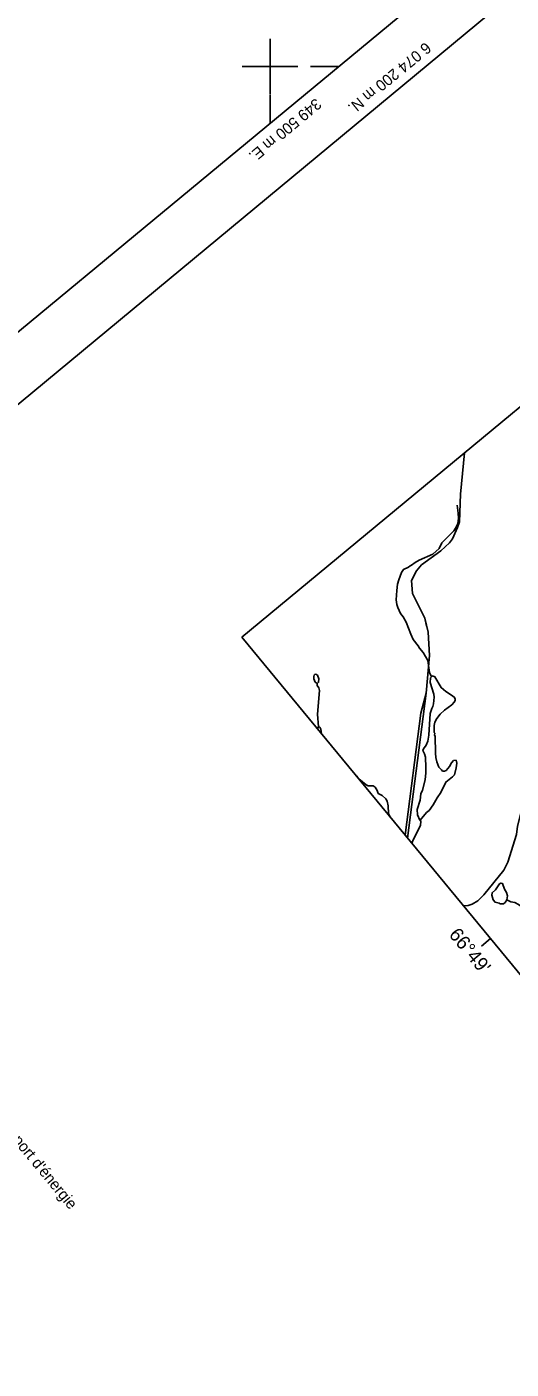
# Model space of a CAD drawing. Extents: x 347312 to 350503, y 6073086 to 6076432.
# Drawn here: x 349412.5 to 349586.7, y 6073732 to 6074214.3 of the extents above; entities that cross this region are included whole.
import ezdxf

# ---------------------------------------------------------------- set-up
doc = ezdxf.new("R2010")
doc.units = 0
for name, color, linetype in [('Level 60', 7, 'Continuous'), ('Level 61', 7, 'Continuous'), ('Level 63', 7, 'Continuous')]:
    doc.layers.add(name, color=color, linetype=linetype)

msp = doc.modelspace()

# ---------------------------------------------------------------- linework, layer by layer
at = {"layer": 'Level 60'}
for p, q in [((349514.56, 6074200), (349524.56, 6074200)), ((349500, 6074189.71), (349500, 6074179.71))]:
    msp.add_line(p, q, dxfattribs=at)
for points in [[(348779.44, 6073584.28), (350085.28, 6074663.34), (348652.09, 6076397.74), (347346.25, 6075318.68)], [(350097.64, 6074648.45), (350470.23, 6074198.33), (349166.42, 6073119.09), (348793.83, 6073569.21)]]:
    msp.add_lwpolyline(points, close=True, dxfattribs=at)
at = {"layer": 'Level 61'}
for p, q in [((349500, 6074210), (349500, 6074190)), ((349490, 6074200), (349510, 6074200))]:
    msp.add_line(p, q, dxfattribs=at)
at = {"layer": 'Level 63'}
for p, q in [((349549.45, 6073922.83), (349556.11, 6073974.87)), ((349579.28, 6073886.73), (349576, 6073884.02))]:
    msp.add_line(p, q, dxfattribs=at)
msp.add_lwpolyline([(349489.82, 6073994.99), (349706.59, 6073732.65), (349903.35, 6073895.24), (349686.57, 6074157.57)], close=True, dxfattribs=at)
for points in [[(349556.11, 6073974.87), (349557.36, 6073988.44), (349556.87, 6073996.73), (349555.61, 6074001.76), (349551.26, 6074010.63), (349550.92, 6074015.3), (349552.64, 6074018.82), (349554.49, 6074020.94), (349561.41, 6074025.98), (349564.57, 6074028.91), (349565.67, 6074030.33), (349567.47, 6074034.36), (349568.08, 6074036.4), (349568.52, 6074046.41), (349569.99, 6074061.24)], [(349567.3, 6074042.46), (349567.68, 6074039.51), (349567.75, 6074037.78), (349567.49, 6074035.78), (349566.94, 6074034.48), (349566.13, 6074033.24), (349561.84, 6074028.87), (349560.85, 6074026.89), (349558.58, 6074024.82), (349553.66, 6074022.61), (349552.2, 6074021.84), (349550.87, 6074020.85), (349550.37, 6074020.66), (349549.76, 6074020.13), (349547.97, 6074019.31), (349547.33, 6074018.2), (349546.29, 6074015.54), (349545.87, 6074014.07), (349545.54, 6074011.75), (349545.3, 6074008.35), (349545.56, 6074006.72), (349545.91, 6074005.59), (349546.97, 6074003.49), (349547.9, 6074002.33), (349548.94, 6074000.39), (349550.59, 6073996.11), (349551.49, 6073994.21), (349553.31, 6073991.85), (349553.75, 6073991.01), (349555.09, 6073989.46), (349556.76, 6073986.66), (349557.31, 6073982.27), (349558.04, 6073980.79)], [(349551.56, 6074010), (349555.61, 6074001.76), (349556.32, 6073998.93)], [(349615.7, 6073990.32), (349613.36, 6073988.48), (349611.61, 6073985.95), (349611.09, 6073980.65), (349609.87, 6073977.74), (349607.92, 6073975.06), (349602.95, 6073969.88), (349599.93, 6073965.27), (349598.84, 6073960.55), (349598.56, 6073955.83), (349593.82, 6073943.99), (349591.38, 6073936.59), (349589, 6073927.11), (349588.68, 6073924.15), (349585.58, 6073914.21), (349584.03, 6073911.25), (349576.84, 6073902.36), (349574.68, 6073900.22), (349572.74, 6073899.12), (349571.25, 6073898.59), (349569.6, 6073898.44)], [(349516.96, 6073978.35), (349517.43, 6073978.78), (349517.58, 6073980.03), (349517.06, 6073981.3), (349516.65, 6073981.62), (349516.2, 6073981.71), (349515.83, 6073981.36), (349515.68, 6073980.86), (349515.73, 6073979.97), (349516.2, 6073978.83), (349516.96, 6073978.35)], [(349516.96, 6073978.35), (349516.97, 6073977.65), (349517.57, 6073976.82), (349517.72, 6073975.8), (349517.09, 6073967.28), (349517.41, 6073962.76)], [(349553.81, 6073929.22), (349553.97, 6073929.29), (349556.22, 6073931.94), (349557.19, 6073932.76), (349558.66, 6073934.74), (349560.11, 6073937.24), (349561.46, 6073939.23), (349563.25, 6073942.93), (349565.66, 6073944.83), (349566.28, 6073945.54), (349566.94, 6073948.07), (349567.22, 6073949.7), (349566.89, 6073950.74), (349566.03, 6073950.66), (349565.2, 6073949.79), (349564.51, 6073948.48), (349563.28, 6073947.07), (349562.8, 6073946.8), (349562.05, 6073946.86), (349561.61, 6073947.27), (349560.76, 6073948.34), (349559.96, 6073950.25), (349559.62, 6073951.77), (349559.5, 6073953.3), (349559.34, 6073959.47), (349559.19, 6073959.73), (349559.21, 6073960.45), (349559.06, 6073960.71), (349558.97, 6073963.3), (349559.32, 6073964.5), (349559.98, 6073965.78), (349561.16, 6073967.31), (349562.79, 6073968.82), (349565.35, 6073970.73), (349566.21, 6073971.63), (349566.52, 6073972.26), (349566.52, 6073972.74), (349566.35, 6073973.37), (349565.6, 6073973.97), (349563.17, 6073975.41), (349561.55, 6073976.9), (349559.28, 6073980.74), (349558.37, 6073981.05), (349558.04, 6073980.79), (349557.69, 6073980.35), (349557.55, 6073978.67), (349558.86, 6073974.55), (349559, 6073973.41), (349558.8, 6073970.98), (349558.57, 6073970.04), (349558.19, 6073969.35), (349557.59, 6073967.58), (349557.16, 6073959.75), (349556.7, 6073957.65), (349556.11, 6073956.21), (349555.14, 6073954.9), (349554.95, 6073954.32), (349555.54, 6073953.1), (349555.88, 6073951.91), (349555.99, 6073948.14), (349556, 6073946.2), (349555.77, 6073943.68), (349554.86, 6073940.03), (349554.27, 6073938.65), (349554.01, 6073936.44), (349552.92, 6073933.02), (349553.01, 6073931.19), (349553.81, 6073929.22)], [(349556.11, 6073974.87), (349554.24, 6073967.69), (349548.62, 6073923.83)], [(349517.41, 6073962.76), (349517.19, 6073962.42), (349517.19, 6073961.86)], [(349517.41, 6073962.76), (349517.88, 6073962.64), (349518.2, 6073961.97), (349518.51, 6073960.27)], [(349531.02, 6073945.13), (349531.15, 6073945.04), (349531.64, 6073944.38)], [(349531.91, 6073944.05), (349534.58, 6073941.94), (349535.23, 6073941.6), (349537.05, 6073941.57), (349537.78, 6073941.06), (349538.49, 6073939.88), (349538.91, 6073938.86), (349540.37, 6073938.12), (349541.59, 6073936.86), (349542.07, 6073936.04), (349542.42, 6073934.43), (349542.65, 6073931.67), (349543.21, 6073930.38)], [(349553.97, 6073929.29), (349554.26, 6073928.93), (349554.13, 6073927.31), (349551.62, 6073922.39), (349551, 6073920.94)], [(349584.58, 6073899.64), (349585.2, 6073900.57), (349585.35, 6073902.1), (349585.01, 6073903.29), (349584.29, 6073904.4), (349583.56, 6073906.49), (349583.06, 6073906.63), (349582.58, 6073906.36), (349581.05, 6073904.17), (349579.84, 6073903.16), (349579.8, 6073902.32), (349580.25, 6073900.66), (349580.93, 6073899.74), (349582.37, 6073899.42), (349582.74, 6073899.16), (349583.95, 6073899.14), (349584.58, 6073899.64)], [(349585.2, 6073900.57), (349586.55, 6073899.9), (349588.09, 6073899.66), (349589.38, 6073898.99), (349590.65, 6073897.94), (349591.84, 6073895.4), (349592.87, 6073894.16), (349593.45, 6073893.1), (349593.75, 6073892.09), (349593.89, 6073890.89), (349594.52, 6073889.34), (349595.64, 6073887.78), (349596.93, 6073887.12)]]:
    msp.add_lwpolyline(points, dxfattribs=at)

# ---------------------------------------------------------------- texts
at = {"layer": 'Level 61'}
for s, rotation, p in [('6 074 200 m N.', 219.3644, (349555.88, 6074208.99)), ('349 500 m E. ', 219.813, (349516.38, 6074188.84))]:
    msp.add_text(s, height=4, rotation=rotation, dxfattribs=at).set_placement(p)
at = {"layer": 'Level 63'}
for s, height, rotation, p in [("66°49'", 4.967, 309.568, (349564.07, 6073888)), ("Pylône, ligne de transport d'énergie", 4, 309.5735, (349374.42, 6073853.81))]:
    msp.add_text(s, height=height, rotation=rotation, dxfattribs=at).set_placement(p)

doc.saveas('drawing.dxf')
